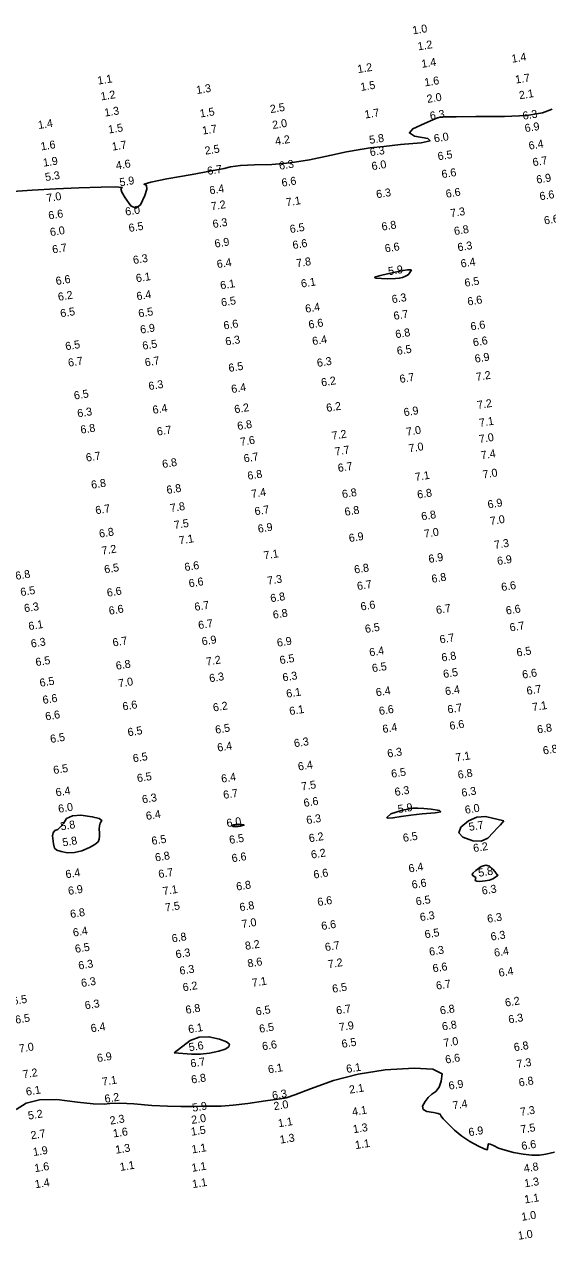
# Model space of a CAD drawing. Extents: x 988130 to 1132882, y 654656 to 841453.
# Drawn here: x 1106262 to 1106589, y 665991 to 666750 of the extents above; entities that cross this region are included whole.
import ezdxf

# ---------------------------------------------------------------- set-up
doc = ezdxf.new("R2010")
doc.units = 0
doc.layers.add('V-TOPO-MINR', color=7, linetype='Continuous')
doc.layers.add('V-TOPO-SOUN', color=7, linetype='Continuous')

msp = doc.modelspace()

# ---------------------------------------------------------------- linework, layer by layer
at = {"layer": 'V-TOPO-MINR'}
for points in [[(1106592.14, 666697), (1106586.2, 666694.7), (1106576.29, 666693.17), (1106562.4, 666692.41), (1106544.54, 666692.4), (1106532.15, 666692.38), (1106525.24, 666692.34), (1106523.79, 666692.28), (1106522.52, 666692.16), (1106521.44, 666691.97), (1106520.53, 666691.73), (1106517.5, 666690.47), (1106512.33, 666688.19), (1106505.03, 666684.89), (1106502.96, 666682.21), (1106506.13, 666680.14), (1106514.54, 666678.69), (1106515.89, 666677.34), (1106510.2, 666676.08), (1106497.45, 666674.91), (1106486.85, 666673.82), (1106478.4, 666672.82), (1106472.1, 666671.89), (1106463.68, 666670.35), (1106453.14, 666668.2), (1106440.48, 666665.44), (1106428.42, 666663.54), (1106416.94, 666662.5), (1106406.06, 666662.32), (1106397.46, 666661.86), (1106391.15, 666661.1), (1106387.13, 666660.06), (1106379.16, 666658.44), (1106367.24, 666656.26), (1106351.39, 666653.51), (1106341.34, 666651.46), (1106337.09, 666650.11), (1106338.65, 666649.46), (1106338.8, 666647.1), (1106337.56, 666643.05), (1106334.91, 666637.3), (1106331.98, 666635.15), (1106328.77, 666636.6), (1106325.27, 666641.66), (1106323.22, 666645.27), (1106322.59, 666647.45), (1106323.4, 666648.19), (1106319.3, 666648.51), (1106310.29, 666648.42), (1106296.37, 666647.91), (1106281.99, 666647.25), (1106267.16, 666646.43), (1106251.87, 666645.44)], [(1106593.66, 666045.38), (1106588.29, 666044.09), (1106584.29, 666043.43), (1106579.56, 666043.38), (1106574.11, 666043.97), (1106567.94, 666045.17), (1106562.78, 666046.49), (1106558.64, 666047.92), (1106555.5, 666049.47), (1106553.39, 666050.34), (1106552.28, 666050.54), (1106552.2, 666050.05), (1106552.11, 666049.55), (1106552.02, 666049.05), (1106551.92, 666048.54), (1106551.83, 666047.99), (1106551.72, 666047.4), (1106551.61, 666046.78), (1106549.74, 666047.35), (1106546.12, 666049.1), (1106540.74, 666052.05), (1106535.75, 666055.38), (1106531.16, 666059.11), (1106526.98, 666063.24), (1106524.12, 666066.23), (1106522.59, 666068.08), (1106522.39, 666068.81), (1106520.85, 666069.48), (1106517.97, 666070.1), (1106513.76, 666070.68), (1106511.48, 666072.04), (1106511.14, 666074.17), (1106512.72, 666077.08), (1106514.65, 666079.57), (1106516.92, 666081.62), (1106519.53, 666083.24), (1106521.46, 666085.9), (1106522.72, 666089.61), (1106523.31, 666094.35), (1106517.67, 666097.11), (1106505.81, 666097.89), (1106487.73, 666096.68), (1106470.93, 666094.1), (1106455.41, 666090.15), (1106441.17, 666084.84), (1106431.34, 666081.22), (1106425.93, 666079.31), (1106424.93, 666079.09), (1106420.6, 666078.43), (1106412.94, 666077.32), (1106401.96, 666075.76), (1106392.73, 666074.71), (1106385.26, 666074.15), (1106379.55, 666074.1), (1106373.45, 666074.03), (1106366.96, 666073.92), (1106360.08, 666073.8), (1106351.73, 666074.01), (1106341.91, 666074.55), (1106330.62, 666075.44), (1106321.89, 666075.86), (1106315.71, 666075.82), (1106312.08, 666075.3), (1106305.35, 666075.54), (1106295.5, 666076.53), (1106282.55, 666078.27), (1106271.83, 666078.1), (1106263.35, 666076.03), (1106257.11, 666072.05)]]:
    msp.add_lwpolyline(points, dxfattribs=at)
for points in [[(1106489.16, 666591.01), (1106494.26, 666591.16), (1106496.56, 666591.45), (1106498.6, 666591.96), (1106500.39, 666592.69), (1106501.69, 666593.35), (1106502.51, 666593.94), (1106502.84, 666594.47), (1106503.22, 666595.06), (1106503.65, 666595.71), (1106504.14, 666596.41), (1106503.53, 666596.73), (1106501.82, 666596.65), (1106499.02, 666596.18), (1106495.13, 666595.42), (1106490.16, 666594.37), (1106484.11, 666593.02), (1106481.31, 666592.05), (1106481.76, 666591.45)], [(1106491.34, 666256.84), (1106498.52, 666258.98), (1106501.92, 666259.74), (1106505.12, 666260.18), (1106508.14, 666260.3), (1106511.91, 666260.1), (1106516.44, 666259.59), (1106521.72, 666258.76), (1106522.56, 666258), (1106518.95, 666257.3), (1106510.89, 666256.67), (1106503.82, 666255.95), (1106497.72, 666255.12), (1106492.6, 666254.2), (1106489.62, 666253.98), (1106488.77, 666254.47)], [(1106280.44, 666238.01), (1106279.84, 666243), (1106280.24, 666244.92), (1106281.32, 666246.26), (1106283.1, 666247.02), (1106284.92, 666248.53), (1106286.77, 666250.77), (1106288.66, 666253.76), (1106292.27, 666255.46), (1106297.61, 666255.86), (1106304.67, 666254.96), (1106309.04, 666253.86), (1106310.72, 666252.54), (1106309.72, 666251.01), (1106309.13, 666249.24), (1106308.98, 666247.21), (1106309.25, 666244.94), (1106309.24, 666242.87), (1106308.95, 666241), (1106308.38, 666239.32), (1106306.39, 666237.54), (1106302.98, 666235.67), (1106298.16, 666233.7), (1106293.6, 666232.63), (1106289.33, 666232.46), (1106285.33, 666233.19), (1106282.56, 666234.13), (1106281.03, 666235.29)], [(1106392.69, 666248.79), (1106394.67, 666248.82), (1106395.84, 666248.92), (1106397.18, 666249.11), (1106398.71, 666249.37), (1106399.46, 666249.6), (1106399.45, 666249.79), (1106398.68, 666249.93), (1106397.89, 666250.05), (1106397.09, 666250.13), (1106396.28, 666250.18), (1106395.32, 666250.16), (1106394.21, 666250.09), (1106392.94, 666249.95), (1106392.21, 666249.74), (1106392.02, 666249.47)], [(1106561.95, 666252.33), (1106559.78, 666249.97), (1106557.94, 666247.96), (1106555.36, 666245.12), (1106552.04, 666241.45), (1106547.77, 666239.73), (1106542.56, 666239.95), (1106536.4, 666242.13), (1106533.91, 666244.92), (1106535.1, 666248.34), (1106539.95, 666252.38), (1106545.1, 666254.62), (1106550.52, 666255.06)], [(1106544.54, 666216.91), (1106544.08, 666215.18), (1106544.99, 666214.68), (1106547.03, 666214.55), (1106550.21, 666214.78), (1106552.91, 666215.3), (1106555.12, 666216.09), (1106556.85, 666217.15), (1106557.85, 666217.98), (1106558.11, 666218.56), (1106557.63, 666218.9), (1106557.3, 666219.22), (1106557.11, 666219.52), (1106557.05, 666219.81), (1106556.36, 666220.67), (1106555.04, 666222.09), (1106553.09, 666224.09), (1106550.67, 666224.64), (1106547.78, 666223.75), (1106544.42, 666221.42), (1106542.57, 666219.63), (1106542.22, 666218.36)], [(1106355.86, 666107.48), (1106365.92, 666115.12), (1106371.49, 666117.16), (1106377.62, 666117.42), (1106384.28, 666115.9), (1106388.58, 666114.35), (1106390.51, 666112.79), (1106390.08, 666111.2), (1106387.85, 666109.74), (1106383.83, 666108.42), (1106378.02, 666107.23), (1106372.32, 666106.6), (1106366.75, 666106.52)]]:
    msp.add_lwpolyline(points, close=True, dxfattribs=at)

# ---------------------------------------------------------------- texts
at = {"layer": 'V-TOPO-SOUN'}
for s, p in [('1.0', (1106505.22, 666743.8)), ('1.2', (1106508.45, 666733.8)), ('1.4', (1106510.8, 666722.87)), ('1.4', (1106567.15, 666726.07)), ('1.2', (1106470.84, 666719.61)), ('1.1', (1106308.36, 666712.41)), ('1.3', (1106370.06, 666706.52)), ('1.5', (1106472.72, 666708.46)), ('1.6', (1106512.67, 666711.29)), ('1.7', (1106569.46, 666713.03)), ('1.2', (1106310.34, 666702.53)), ('2.0', (1106514.21, 666700.96)), ('2.1', (1106571.85, 666703.23)), ('1.3', (1106312.64, 666692.41)), ('1.5', (1106372.3, 666691.84)), ('2.5', (1106416.22, 666694.61)), ('1.7', (1106475.32, 666691.2)), ('1.4', (1106271.18, 666684.65)), ('2.0', (1106417.6, 666684.66)), ('6.3', (1106516.09, 666690.42)), ('6.3', (1106574.1, 666690.43)), ('1.5', (1106315.04, 666681.83)), ('1.7', (1106373.81, 666681.16)), ('6.0', (1106518.62, 666676.26)), ('6.9', (1106575.38, 666682.67)), ('1.6', (1106272.86, 666671.28)), ('1.7', (1106317.35, 666671.14)), ('2.5', (1106375.41, 666668.61)), ('4.2', (1106419.41, 666674.57)), ('5.8', (1106478.2, 666675.35)), ('6.4', (1106577.88, 666671.75)), ('1.9', (1106274.29, 666661.12)), ('6.3', (1106478.56, 666667.65)), ('6.5', (1106521, 666665.09)), ('6.7', (1106580.32, 666661.39)), ('4.6', (1106319.82, 666659.37)), ('6.7', (1106376.97, 666655.95)), ('6.3', (1106421.84, 666659.17)), ('6.0', (1106479.67, 666658.92)), ('6.6', (1106523.38, 666653.92)), ('5.3', (1106275.58, 666652.1)), ('5.9', (1106322.12, 666648.84)), ('6.6', (1106423.4, 666648.6)), ('6.9', (1106582.67, 666650.55)), ('7.0', (1106276.5, 666638.98)), ('6.4', (1106378.31, 666643.82)), ('6.3', (1106482.55, 666641.38)), ('6.6', (1106526.04, 666641.66)), ('6.6', (1106584.66, 666640.12)), ('6.0', (1106325.68, 666630.51)), ('7.2', (1106379.29, 666633.85)), ('7.1', (1106426.17, 666636.35)), ('6.6', (1106277.66, 666628.12)), ('7.3', (1106528.89, 666629.54)), ('6.6', (1106587.47, 666624.97)), ('6.0', (1106278.67, 666617.69)), ('6.5', (1106327.82, 666620.3)), ('6.3', (1106380.34, 666622.77)), ('6.5', (1106428.54, 666619.62)), ('6.8', (1106485.91, 666621.13)), ('6.8', (1106531.2, 666618.36)), ('6.9', (1106381.53, 666610.51)), ('6.6', (1106430.27, 666609.65)), ('6.3', (1106533.38, 666608.24)), ('6.7', (1106280.04, 666606.9)), ('6.3', (1106330.56, 666600.27)), ('6.6', (1106487.92, 666607.51)), ('6.4', (1106382.92, 666597.7)), ('7.8', (1106432.55, 666598.27)), ('5.9', (1106490.04, 666593.28)), ('6.4', (1106535.37, 666598.07)), ('6.6', (1106282.24, 666587.18)), ('6.1', (1106332.37, 666588.89)), ('6.1', (1106435.57, 666585.53)), ('6.5', (1106537.75, 666586.03)), ('6.4', (1106332.71, 666577.68)), ('6.1', (1106385.07, 666584.45)), ('6.2', (1106283.64, 666577.28)), ('6.5', (1106385.61, 666573.77)), ('6.4', (1106438.19, 666569.84)), ('6.3', (1106492.27, 666575.79)), ('6.6', (1106539.58, 666574.35)), ('6.5', (1106285.1, 666566.96)), ('6.5', (1106333.9, 666566.92)), ('6.7', (1106493.41, 666565.39)), ('6.9', (1106335.04, 666556.78)), ('6.6', (1106387.1, 666559.36)), ('6.6', (1106440.25, 666559.92)), ('6.6', (1106541.49, 666558.75)), ('6.3', (1106388.28, 666549.4)), ('6.4', (1106442.55, 666549.59)), ('6.8', (1106494.54, 666553.9)), ('6.6', (1106543, 666548.84)), ('6.5', (1106288.26, 666546.39)), ('6.5', (1106336.42, 666546.74)), ('6.5', (1106495.44, 666543.52)), ('6.7', (1106289.97, 666536.11)), ('6.7', (1106337.92, 666536.31)), ('6.5', (1106390.22, 666532.84)), ('6.3', (1106445.51, 666535.98)), ('6.9', (1106544.13, 666538.62)), ('6.7', (1106497.17, 666525.97)), ('7.2', (1106544.91, 666527.23)), ('6.3', (1106340.24, 666521.52)), ('6.4', (1106391.96, 666519.65)), ('6.2', (1106448.14, 666523.79)), ('6.5', (1106293.62, 666515.59)), ('7.2', (1106545.65, 666509.64)), ('6.3', (1106295.74, 666504.45)), ('6.4', (1106342.79, 666506.64)), ('6.2', (1106393.88, 666507.01)), ('6.2', (1106451.37, 666507.88)), ('6.9', (1106499.75, 666505.12)), ('6.8', (1106297.72, 666494.25)), ('6.8', (1106395.7, 666496.55)), ('7.1', (1106546.88, 666498.53)), ('6.7', (1106345.47, 666493.08)), ('7.6', (1106397.5, 666486.65)), ('7.2', (1106454.8, 666490.48)), ('7.0', (1106501.3, 666492.92)), ('7.0', (1106546.83, 666488.4)), ('7.7', (1106456.69, 666480.59)), ('7.0', (1106502.89, 666482.6)), ('6.7', (1106301.11, 666476.82)), ('6.8', (1106348.77, 666472.8)), ('6.7', (1106399.76, 666476.29)), ('7.4', (1106547.98, 666478.25)), ('6.8', (1106402.07, 666465.45)), ('6.7', (1106458.56, 666470.35)), ('7.1', (1106506.76, 666464.7)), ('7.0', (1106549.14, 666466.25)), ('6.8', (1106304.37, 666459.83)), ('6.8', (1106351.47, 666456.62)), ('7.4', (1106404.43, 666454.11)), ('6.8', (1106461.18, 666453.97)), ('6.8', (1106508.18, 666453.7)), ('6.7', (1106307.04, 666443.89)), ('7.8', (1106353.75, 666445.27)), ('6.7', (1106406.53, 666443.24)), ('6.8', (1106462.8, 666442.94)), ('6.9', (1106552.21, 666447.52)), ('7.5', (1106356.18, 666434.67)), ('6.8', (1106510.71, 666440.1)), ('7.0', (1106553.7, 666437.19)), ('6.8', (1106309.34, 666429.29)), ('6.9', (1106408.55, 666432.34)), ('6.9', (1106465.45, 666426.52)), ('7.0', (1106512.47, 666429.19)), ('7.2', (1106310.96, 666418.63)), ('7.1', (1106359.3, 666425.07)), ('7.3', (1106556.3, 666422.27)), ('7.1', (1106412.28, 666415.68)), ('6.9', (1106515.22, 666413.5)), ('6.9', (1106558.13, 666412.17)), ('6.8', (1106257.04, 666402.92)), ('6.5', (1106312.56, 666406.98)), ('6.6', (1106362.68, 666408.39)), ('6.8', (1106468.78, 666406.87)), ('6.6', (1106365.38, 666398.23)), ('7.3', (1106414.49, 666399.86)), ('6.7', (1106470.58, 666396.52)), ('6.8', (1106517.12, 666401.05)), ('6.6', (1106560.7, 666395.91)), ('6.5', (1106260.16, 666392.76)), ('6.6', (1106314.22, 666392.38)), ('6.8', (1106416.39, 666388.92)), ('6.3', (1106262.47, 666382.67)), ('6.6', (1106315.42, 666381.14)), ('6.7', (1106368.94, 666383.54)), ('6.6', (1106472.78, 666383.75)), ('6.7', (1106519.96, 666381.57)), ('6.6', (1106563.59, 666381.21)), ('6.8', (1106417.96, 666378.59)), ('6.1', (1106265.19, 666371.49)), ('6.7', (1106371.29, 666372.12)), ('6.5', (1106475.55, 666369.73)), ('6.7', (1106565.99, 666370.66)), ('6.3', (1106266.7, 666360.56)), ('6.7', (1106317.81, 666361.26)), ('6.9', (1106373.5, 666361.96)), ('6.9', (1106420.52, 666361.12)), ('6.7', (1106522.2, 666363.19)), ('6.5', (1106422.21, 666350.25)), ('6.4', (1106478.25, 666355.1)), ('6.8', (1106523.34, 666351.88)), ('6.5', (1106570.27, 666355)), ('6.5', (1106269.61, 666349.02)), ('6.8', (1106319.82, 666346.75)), ('7.2', (1106376.23, 666349.32)), ('6.5', (1106479.92, 666345.22)), ('6.5', (1106272.19, 666336.09)), ('7.0', (1106321.35, 666335.73)), ('6.3', (1106378.19, 666338.91)), ('6.3', (1106424, 666339.43)), ('6.5', (1106524.4, 666341.59)), ('6.6', (1106573.81, 666341.22)), ('6.1', (1106426.36, 666329.28)), ('6.4', (1106482.33, 666330.13)), ('6.4', (1106525.61, 666330.8)), ('6.7', (1106576.56, 666331.07)), ('6.6', (1106274.05, 666325.38)), ('6.6', (1106323.98, 666321.32)), ('6.2', (1106380.54, 666320.63)), ('6.7', (1106527.09, 666319.45)), ('7.1', (1106580.09, 666320.88)), ('6.6', (1106275.7, 666315.12)), ('6.1', (1106428.26, 666318.42)), ('6.6', (1106484.29, 666318.46)), ('6.5', (1106327.19, 666305.17)), ('6.5', (1106381.93, 666306.78)), ('6.4', (1106486.47, 666307.22)), ('6.6', (1106528.36, 666309.19)), ('6.8', (1106583.15, 666306.94)), ('6.5', (1106278.79, 666301)), ('6.3', (1106431.18, 666298.3)), ('6.5', (1106330.45, 666288.89)), ('6.4', (1106383.23, 666295.62)), ('6.3', (1106489.49, 666291.87)), ('7.1', (1106532.15, 666289.4)), ('6.8', (1106586.75, 666293.77)), ('6.5', (1106280.71, 666281.55)), ('6.4', (1106433.65, 666283.76)), ('6.5', (1106333.05, 666276.49)), ('6.4', (1106385.67, 666276.16)), ('6.5', (1106491.91, 666279.22)), ('6.8', (1106533.53, 666278.6)), ('6.4', (1106282.2, 666267.61)), ('6.7', (1106386.93, 666266.05)), ('7.5', (1106435.71, 666271.3)), ('6.3', (1106494.07, 666267.88)), ('6.3', (1106535.84, 666267.4)), ('6.3', (1106336.19, 666263.26)), ('6.6', (1106437.2, 666261.04)), ('6.0', (1106283.78, 666257.36)), ('6.4', (1106338.62, 666252.88)), ('5.9', (1106496.08, 666257.17)), ('6.0', (1106537.95, 666256.71)), ('5.8', (1106285.19, 666246.39)), ('6.0', (1106388.99, 666248.43)), ('6.3', (1106438.89, 666250.29)), ('5.7', (1106540.41, 666246.07)), ('5.8', (1106286.39, 666236.37)), ('6.5', (1106342.12, 666237.32)), ('6.5', (1106390.68, 666237.93)), ('6.2', (1106440.46, 666238.96)), ('6.5', (1106499.26, 666239.17)), ('6.2', (1106441.82, 666228.73)), ('6.2', (1106543.16, 666232.78)), ('6.8', (1106344.32, 666226.95)), ('6.6', (1106392.22, 666226.45)), ('6.4', (1106288.36, 666216.43)), ('6.7', (1106346.42, 666216.57)), ('6.6', (1106443.34, 666216.26)), ('6.4', (1106502.79, 666220.05)), ('5.8', (1106546.35, 666217.36)), ('6.9', (1106289.96, 666206.05)), ('7.1', (1106349.19, 666205.92)), ('6.8', (1106395.06, 666208.75)), ('6.6', (1106504.76, 666209.96)), ('6.3', (1106548.55, 666206.2)), ('6.6', (1106445.8, 666199.06)), ('6.5', (1106507.29, 666199.5)), ('6.8', (1106291.26, 666191.61)), ('7.5', (1106350.6, 666195.64)), ('6.8', (1106397.11, 666195.88)), ('7.0', (1106398.49, 666185.33)), ('6.6', (1106448.23, 666184.11)), ('6.3', (1106509.85, 666189.68)), ('6.3', (1106551.91, 666188.6)), ('6.4', (1106292.98, 666180.02)), ('6.8', (1106354.76, 666176.34)), ('6.5', (1106512.83, 666178.9)), ('6.3', (1106554.11, 666177.48)), ('6.5', (1106294.28, 666169.83)), ('8.2', (1106400.58, 666171.68)), ('6.7', (1106450.52, 666170.93)), ('6.3', (1106515.65, 666168.03)), ('6.4', (1106556.24, 666167.41)), ('6.3', (1106357.18, 666166.44)), ('8.6', (1106402.12, 666160.73)), ('7.2', (1106452.37, 666160.22)), ('6.3', (1106296.41, 666159.42)), ('6.3', (1106359.63, 666156.16)), ('6.6', (1106517.8, 666157.64)), ('6.4', (1106559.1, 666154.89)), ('6.3', (1106298.09, 666148.49)), ('6.2', (1106361.63, 666145.78)), ('7.1', (1106404.88, 666148.61)), ('6.5', (1106455.06, 666144.9)), ('6.7', (1106519.98, 666146.84)), ('6.5', (1106255.13, 666137.28)), ('6.3', (1106300.4, 666134.52)), ('6.8', (1106363.39, 666131.73)), ('6.5', (1106407.27, 666130.73)), ('6.7', (1106457.54, 666131.35)), ('6.8', (1106522.41, 666131.32)), ('6.2', (1106563.1, 666136.23)), ('6.5', (1106256.9, 666125.54)), ('6.3', (1106565.19, 666125.74)), ('6.4', (1106304.12, 666120.19)), ('6.1', (1106365.03, 666119.62)), ('6.5', (1106409.43, 666119.9)), ('7.9', (1106459.35, 666120.9)), ('6.8', (1106523.69, 666121.35)), ('7.0', (1106259.3, 666107.53)), ('5.6', (1106365.41, 666108.34)), ('6.6', (1106411.25, 666108.95)), ('6.5', (1106460.95, 666110.47)), ('7.0', (1106524.63, 666111.04)), ('6.8', (1106568.57, 666108.37)), ('6.9', (1106308.05, 666101.57)), ('6.6', (1106525.73, 666100.66)), ('7.2', (1106261.67, 666091.43)), ('6.7', (1106366.44, 666098.21)), ('6.1', (1106414.93, 666094.52)), ('6.1', (1106463.85, 666094.82)), ('7.3', (1106570.35, 666097.84)), ('7.1', (1106311.23, 666086.8)), ('6.8', (1106366.93, 666088.16)), ('6.9', (1106527.82, 666084.35)), ('6.8', (1106571.67, 666086.31)), ('6.1', (1106263.64, 666080.6)), ('6.2', (1106312.76, 666076.12)), ('6.3', (1106417.48, 666078.29)), ('2.1', (1106465.66, 666081.85)), ('5.9', (1106367.55, 666070.55)), ('2.0', (1106418.44, 666071.51)), ('7.4', (1106530.39, 666071.99)), ('5.2', (1106264.92, 666065.65)), ('2.3', (1106316.04, 666062.51)), ('2.0', (1106366.96, 666062.93)), ('4.1', (1106467.49, 666068.02)), ('7.3', (1106572.52, 666067.98)), ('2.7', (1106266.63, 666053.32)), ('1.6', (1106318.06, 666054.48)), ('1.5', (1106366.73, 666055.55)), ('1.1', (1106421.18, 666060.86)), ('1.3', (1106468.01, 666057.14)), ('6.9', (1106540.26, 666055.27)), ('7.5', (1106572.79, 666057.02)), ('1.3', (1106422.32, 666050.62)), ('1.1', (1106469.35, 666047.21)), ('6.6', (1106573.31, 666046.66)), ('1.9', (1106268.02, 666042.89)), ('1.3', (1106319.57, 666044.33)), ('1.1', (1106367.22, 666044.52)), ('1.6', (1106268.92, 666032.81)), ('1.1', (1106322.3, 666033.57)), ('1.1', (1106367.19, 666033)), ('4.8', (1106574.79, 666032.66)), ('1.3', (1106575.08, 666023.32)), ('1.4', (1106269.2, 666022.76)), ('1.1', (1106367.54, 666022.84)), ('1.1', (1106575.18, 666013.25)), ('1.0', (1106573.3, 666002.38)), ('1.0', (1106571.14, 665990.55))]:
    msp.add_text(s, height=5, rotation=9.0039, dxfattribs=at).set_placement(p)

doc.saveas('drawing.dxf')
